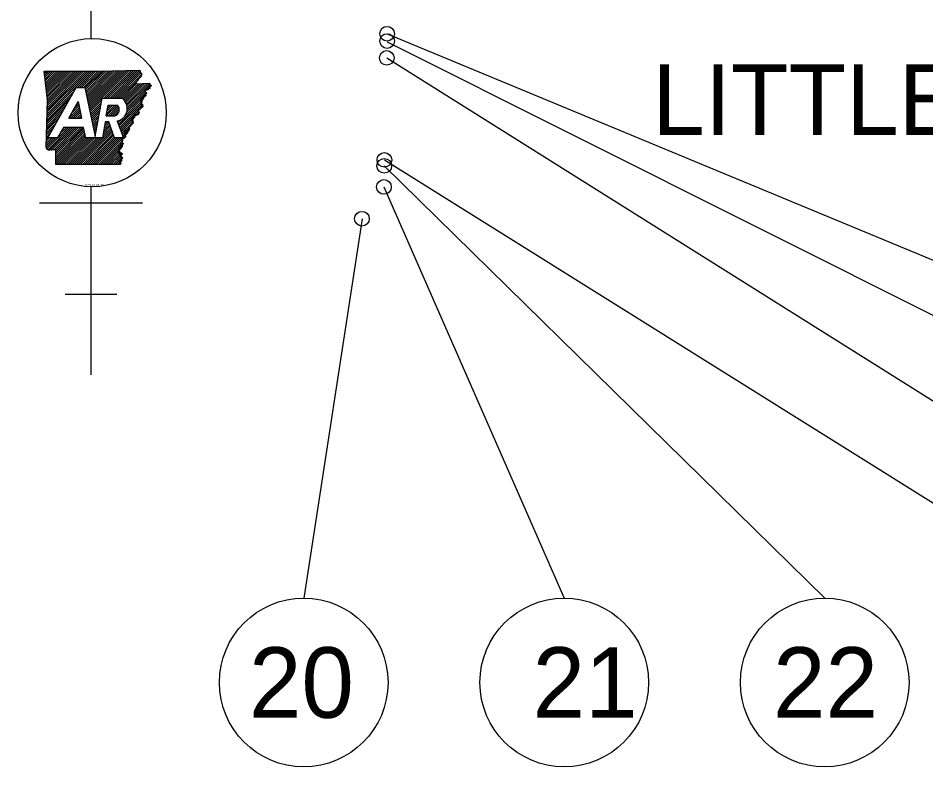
# Model space of a CAD drawing. Extents: x -12863 to 18921, y -8840 to 11152.
# Drawn here: x -1568 to 1521, y -4899 to -2352 of the extents above; entities that cross this region are included whole.
import ezdxf

# ---------------------------------------------------------------- set-up
doc = ezdxf.new("R2010")
doc.units = 0
doc.layers.add('Level 2', color=7, linetype='Continuous')
doc.layers.add('Level 48', color=7, linetype='Continuous')

msp = doc.modelspace()

# ---------------------------------------------------------------- linework, layer by layer
at = {"layer": 'Level 48'}
for p, q in [((-1319.7, -2421.2), (-1319.7, -845.3)), ((-312, -2404.6), (4520.7, -4409.4)), ((-312.1, -2432), (3634.1, -4409.4)), ((-313.2, -2486.8), (2747.5, -4409.4)), ((-1479.3, -2534.1), (-1477.2, -2531.9)), ((-1478.6, -2540.3), (-1470.2, -2531.9)), ((-1477.8, -2546.5), (-1463.2, -2531.9)), ((-1477, -2552.7), (-1456.3, -2531.9)), ((-1476.2, -2558.9), (-1449.3, -2531.9)), ((-1475.5, -2565.1), (-1442.3, -2531.9)), ((-1474.7, -2571.3), (-1435.4, -2532)), ((-1473.9, -2577.5), (-1428.4, -2532)), ((-1473.2, -2583.7), (-1421.5, -2532)), ((-1472.4, -2589.8), (-1414.5, -2532)), ((-1471.6, -2596), (-1407.5, -2532)), ((-1470.8, -2602.2), (-1400.6, -2532)), ((-1470.1, -2608.4), (-1393.6, -2532)), ((-1469.3, -2614.6), (-1386.7, -2532)), ((-1469.1, -2684), (-1316.9, -2531.8)), ((-1468.8, -2676.8), (-1323.8, -2531.9)), ((-1468.6, -2669.6), (-1330.8, -2531.9)), ((-1468.5, -2620.8), (-1379.7, -2532)), ((-1468.3, -2662.4), (-1337.8, -2531.9)), ((-1468.1, -2655.2), (-1344.8, -2531.9)), ((-1467.9, -2648), (-1351.8, -2531.9)), ((-1467.8, -2627), (-1372.7, -2532)), ((-1467.6, -2640.8), (-1358.7, -2531.9)), ((-1467.4, -2633.6), (-1365.7, -2531.9)), ((-1365.6, -2587.6), (-1309.9, -2531.8)), ((-1358.7, -2587.6), (-1302.9, -2531.8)), ((-1351.7, -2587.6), (-1295.9, -2531.8)), ((-1344.7, -2587.6), (-1288.8, -2531.6)), ((-1340.4, -2590.2), (-1281.7, -2531.5)), ((-1339.2, -2595.9), (-1274.6, -2531.4)), ((-1337.9, -2601.7), (-1267.6, -2531.3)), ((-1336.7, -2607.4), (-1260.5, -2531.2)), ((-1335.5, -2613.2), (-1253.4, -2531.1)), ((-1334.2, -2618.9), (-1246.3, -2531)), ((-1333, -2624.6), (-1239.3, -2530.9)), ((-1331.8, -2630.4), (-1232.2, -2530.8)), ((-1330.6, -2636.1), (-1225.1, -2530.7)), ((-1329.3, -2641.8), (-1218, -2530.5)), ((-1328.1, -2647.6), (-1211, -2530.4)), ((-1326.9, -2653.3), (-1203.9, -2530.3)), ((-1325.7, -2659.1), (-1196.8, -2530.2)), ((-1324.4, -2664.8), (-1189.7, -2530)), ((-1276, -2623.4), (-1182.5, -2529.9)), ((-1269.1, -2623.4), (-1175.4, -2529.7)), ((-1262.1, -2623.4), (-1168.3, -2529.5)), ((-1255.1, -2623.4), (-1161.1, -2529.4)), ((-1248.2, -2623.4), (-1154, -2529.2)), ((-1241.2, -2623.4), (-1152.5, -2534.6)), ((-1234.2, -2623.4), (-1149.1, -2538.2)), ((-1227.3, -2623.4), (-1148.2, -2544.3)), ((-1467, -2759.2), (-1369.8, -2587.6)), ((-1369.8, -2587.6), (-1341, -2587.6)), ((-1220.3, -2623.4), (-1164.1, -2567.1)), ((-1214, -2624), (-1165.5, -2575.5)), ((-1210.2, -2627.2), (-1158.1, -2575.1)), ((-1206.8, -2630.7), (-1150.8, -2574.7)), ((-1203.8, -2634.7), (-1143.4, -2574.4)), ((-1201.2, -2639.1), (-1136.1, -2574)), ((-1199.1, -2643.9), (-1128.7, -2573.6)), ((-1197.5, -2649.3), (-1122.1, -2574)), ((-1196.5, -2655.3), (-1118.9, -2577.7)), ((-1122, -2587.7), (-1115.6, -2581.4)), ((-1469.5, -2698.5), (-1384.4, -2613.3)), ((-1469.3, -2691.3), (-1375.3, -2597.3)), ((-1282.3, -2623.4), (-1214.9, -2623.4)), ((-1197.9, -2670.6), (-1134.7, -2607.4)), ((-1196.5, -2662.2), (-1135.5, -2601.3)), ((-1142.5, -2622.2), (-1133.9, -2613.6)), ((-1470, -2712.9), (-1402.6, -2645.4)), ((-1469.8, -2705.7), (-1393.5, -2629.4)), ((-1395.5, -2691.8), (-1363.7, -2635.7)), ((-1395.2, -2691.8), (-1359.4, -2656)), ((-1386.9, -2676.5), (-1360.6, -2650.3)), ((-1377.8, -2660.5), (-1361.8, -2644.5)), ((-1368.7, -2644.4), (-1363.1, -2638.8)), ((-1323.2, -2670.5), (-1283.7, -2631)), ((-1322, -2676.3), (-1285.1, -2639.4)), ((-1320.7, -2682), (-1286.6, -2647.9)), ((-1319.5, -2687.7), (-1288.1, -2656.3)), ((-1267.7, -2684.2), (-1231, -2647.6)), ((-1266.2, -2675.8), (-1238, -2647.6)), ((-1264.8, -2667.4), (-1244.9, -2647.6)), ((-1263.3, -2659), (-1251.9, -2647.6)), ((-1261.8, -2650.5), (-1258.9, -2647.6)), ((-1261.3, -2647.6), (-1229.6, -2647.6)), ((-1260.7, -2684.2), (-1227.1, -2650.7)), ((-1253.7, -2684.2), (-1224.8, -2655.3)), ((-1226.7, -2713.3), (-1149.5, -2636.1)), ((-1224.8, -2718.4), (-1148.2, -2641.8)), ((-1222.9, -2723.5), (-1146.9, -2647.4)), ((-1221, -2728.6), (-1145.6, -2653.1)), ((-1204, -2683.7), (-1150.8, -2630.4)), ((-1470.5, -2727.3), (-1420.8, -2677.6)), ((-1470.3, -2720.1), (-1411.7, -2661.5)), ((-1388.2, -2691.8), (-1358.2, -2661.8)), ((-1381.2, -2691.8), (-1356.9, -2667.5)), ((-1374.3, -2691.8), (-1355.7, -2673.2)), ((-1367.3, -2691.8), (-1354.5, -2679)), ((-1360.3, -2691.8), (-1353.2, -2684.7)), ((-1318.3, -2693.5), (-1289.6, -2664.7)), ((-1317.1, -2699.2), (-1291, -2673.2)), ((-1315.8, -2705), (-1292.5, -2681.6)), ((-1267.7, -2684.2), (-1238.8, -2684.2)), ((-1246.8, -2684.2), (-1223.5, -2661)), ((-1239.8, -2684.2), (-1224.1, -2668.5)), ((-1169.4, -2683.9), (-1159.6, -2674.1)), ((-1471, -2741.7), (-1439, -2709.7)), ((-1470.7, -2734.5), (-1429.9, -2693.6)), ((-1395.5, -2691.8), (-1351.7, -2691.8)), ((-1353.4, -2691.8), (-1352, -2690.5)), ((-1314.6, -2710.7), (-1294, -2690.1)), ((-1313.4, -2716.4), (-1295.4, -2698.5)), ((-1312.1, -2722.2), (-1296.9, -2706.9)), ((-1310.9, -2727.9), (-1298.4, -2715.4)), ((-1276.6, -2735.4), (-1255.8, -2714.6)), ((-1275.1, -2727), (-1257.7, -2709.5)), ((-1273.7, -2718.5), (-1259.7, -2704.6)), ((-1272.2, -2710.1), (-1266.7, -2704.6)), ((-1259.6, -2704.6), (-1271.2, -2704.6)), ((-1239.4, -2759.2), (-1259.6, -2704.6)), ((-1231, -2701.7), (-1209.7, -2759.2)), ((-1230.4, -2703.2), (-1228.3, -2701)), ((-1228.6, -2708.2), (-1215.3, -2695)), ((-1219.2, -2733.7), (-1177.4, -2691.9)), ((-1217.3, -2738.8), (-1178.2, -2699.6)), ((-1215.4, -2743.8), (-1178.9, -2707.4)), ((-1471.5, -2756.1), (-1457.2, -2741.8)), ((-1471.2, -2748.9), (-1448.1, -2725.7)), ((-1469.9, -2796.4), (-1396.7, -2723.2)), ((-1465.8, -2799.2), (-1389.8, -2723.2)), ((-1460.8, -2801.2), (-1382.8, -2723.2)), ((-1452.5, -2799.9), (-1375.8, -2723.2)), ((-1445.5, -2799.8), (-1368.9, -2723.2)), ((-1440, -2801.3), (-1361.9, -2723.2)), ((-1439.8, -2808), (-1354.9, -2723.2)), ((-1439.7, -2814.9), (-1348, -2723.2)), ((-1439.7, -2821.9), (-1344.3, -2726.5)), ((-1439.7, -2828.8), (-1343.1, -2732.2)), ((-1439.7, -2835.8), (-1341.9, -2737.9)), ((-1439.7, -2842.7), (-1340.6, -2743.7)), ((-1413.3, -2723.2), (-1433.7, -2759.2)), ((-1425.8, -2745.2), (-1403.7, -2723.2)), ((-1416.7, -2729.2), (-1410.7, -2723.2)), ((-1345, -2723.2), (-1413.3, -2723.2)), ((-1370, -2849.7), (-1250.2, -2729.9)), ((-1363.1, -2849.7), (-1248.3, -2735)), ((-1356.1, -2849.7), (-1246.4, -2740.1)), ((-1349.2, -2849.7), (-1244.6, -2745.1)), ((-1309.7, -2733.6), (-1299.8, -2723.8)), ((-1308.5, -2739.4), (-1301.3, -2732.2)), ((-1307.2, -2745.1), (-1302.8, -2740.7)), ((-1306, -2750.9), (-1304.3, -2749.1)), ((-1279.6, -2752.3), (-1252.1, -2724.8)), ((-1278.1, -2743.8), (-1254, -2719.7)), ((-1213.5, -2748.9), (-1192.2, -2727.6)), ((-1211.7, -2754), (-1195.2, -2737.5)), ((-1472.5, -2792), (-1439.7, -2759.2)), ((-1472.4, -2784.9), (-1446.7, -2759.2)), ((-1472.2, -2777.7), (-1453.6, -2759.2)), ((-1471.9, -2770.5), (-1460.6, -2759.2)), ((-1471.7, -2763.3), (-1466.2, -2757.8)), ((-1433.7, -2759.2), (-1467, -2759.2)), ((-1439.6, -2849.6), (-1339.4, -2749.4)), ((-1432.6, -2849.6), (-1338.2, -2755.2)), ((-1425.7, -2849.6), (-1335.2, -2759.2)), ((-1418.7, -2849.6), (-1328.3, -2759.2)), ((-1411.7, -2849.6), (-1321.3, -2759.2)), ((-1404.8, -2849.6), (-1314.3, -2759.2)), ((-1397.8, -2849.6), (-1307.4, -2759.2)), ((-1390.9, -2849.7), (-1300.4, -2759.2)), ((-1383.9, -2849.7), (-1293.4, -2759.2)), ((-1377, -2849.7), (-1286.5, -2759.2)), ((-1342.2, -2849.7), (-1242.7, -2750.2)), ((-1280.8, -2759.2), (-1337.3, -2759.2)), ((-1335.2, -2849.8), (-1240.8, -2755.3)), ((-1328.3, -2849.8), (-1237.7, -2759.2)), ((-1321.3, -2849.8), (-1230.7, -2759.2)), ((-1314.4, -2849.8), (-1223.8, -2759.2)), ((-1307.4, -2849.8), (-1216.8, -2759.2)), ((-1300.5, -2849.8), (-1214.5, -2763.8)), ((-1293.5, -2849.8), (-1214.2, -2770.5)), ((-1286.6, -2849.8), (-1213.8, -2777.1)), ((-1209.7, -2759.2), (-1239.4, -2759.2)), ((-1279.6, -2849.8), (-1213.5, -2783.8)), ((-1272.7, -2849.9), (-1225, -2802.2)), ((-1265.7, -2849.9), (-1222.8, -2807)), ((-1258.7, -2849.9), (-1220.7, -2811.8)), ((-1251.8, -2849.9), (-1218.5, -2816.6)), ((-1244.8, -2849.9), (-1216.4, -2821.4)), ((-1237.9, -2849.9), (-1214.6, -2826.6)), ((-1230.9, -2849.9), (-1217.7, -2836.7)), ((-321.4, -2833.9), (2063.8, -4325.4)), ((-1224, -2849.9), (-1220.9, -2846.8)), ((-321.7, -2854.1), (1177.2, -4325.4)), ((-1319.7, -3564.9), (-1319.7, -2925.3)), ((-322.9, -2926.1), (290.7, -4325.4)), ((-1495.1, -2979.7), (-1144.2, -2979.7)), ((-397.5, -3035), (-595.9, -4325.4)), ((-1407.4, -3291.3), (-1232, -3291.3))]:
    msp.add_line(p, q, dxfattribs=at)
for points in [[(-1479.6, -2532), (-1383.5, -2532), (-1299.1, -2531.8), (-1199.7, -2530.3), (-1153.6, -2529.2)], [(-1479.6, -2531.9), (-1383.5, -2532), (-1299.2, -2531.8), (-1199.7, -2530.3), (-1153.6, -2529.2)], [(-1472.6, -2791.9), (-1467.3, -2630.7), (-1479.6, -2531.9)], [(-1469, -2681.3), (-1467.3, -2630.7), (-1479.6, -2532)], [(-1341, -2587.6), (-1305.2, -2754.6), (-1282.3, -2623.4)], [(-1123.4, -2573.3), (-1115.1, -2582), (-1135.8, -2599.1), (-1133.5, -2616.3), (-1151.3, -2628), (-1145.2, -2654.5), (-1158.9, -2667), (-1160.2, -2680.6), (-1176.8, -2686.6), (-1179.4, -2712.2), (-1191.4, -2725), (-1197.2, -2744.4), (-1214.6, -2760.3), (-1213.3, -2788.5), (-1225.2, -2801.8), (-1214.4, -2825.9), (-1221.8, -2849.9)], [(-1167.8, -2575.6), (-1122.7, -2573.3)], [(-1167.8, -2575.6), (-1122.7, -2573.3)], [(-1363.7, -2635.7), (-1351.7, -2691.8)], [(-1267.7, -2684.2), (-1261.3, -2647.6)], [(-1472.6, -2791.9), (-1469, -2681.3)], [(-1271.2, -2704.6), (-1280.8, -2759.2)], [(-1337.3, -2759.2), (-1345, -2723.2)], [(-1221.9, -2850), (-1439.7, -2849.6), (-1439.8, -2801.5)], [(-1221.8, -2849.9), (-1439.7, -2849.6), (-1439.8, -2801.5)]]:
    msp.add_lwpolyline(points, dxfattribs=at)
for centre, radius in [((-312, -2404.6), 25), ((-312, -2429.7), 25), ((-313.2, -2486.8), 25), ((-321.4, -2833.9), 25), ((-321.7, -2854.1), 25), ((-322.9, -2926.1), 25), ((-397.6, -3034.1), 25), ((-595.9, -4612.3), 286.9), ((290.7, -4612.3), 286.9), ((1177.2, -4612.3), 286.9)]:
    msp.add_circle(centre, radius, dxfattribs=at)
msp.add_ellipse((-1315.6, -2673.3), major_axis=(252.1, 0), ratio=0.999976, dxfattribs=at)
for centre, major_axis, start_param, end_param in [((-1239.9, -2659), (-43.6, 0), 1.777838, 4.099264), ((-1245.7, -2663), (-22.3, 0), 1.887169, 3.90762)]:
    msp.add_ellipse(centre, major_axis=major_axis, ratio=0.999987, start_param=start_param, end_param=end_param, dxfattribs=at)
for points in [[(-1153.6, -2529.2), (-1153.3, -2531.8), (-1152.5, -2533.2), (-1152.4, -2535.7), (-1151.3, -2536.8), (-1149.5, -2537.8), (-1148.1, -2539.5), (-1147.7, -2541.5), (-1148.2, -2543.6), (-1148.3, -2546), (-1148.5, -2548), (-1148.9, -2549.8), (-1150.3, -2551.3), (-1151.6, -2552.4), (-1152.9, -2553.6), (-1153.8, -2554.9), (-1155.3, -2556.3), (-1156.9, -2557.9), (-1158.2, -2559.1), (-1159.4, -2560.8), (-1160, -2562.6), (-1161.3, -2564), (-1162.4, -2565.2), (-1163.8, -2566.8), (-1164.5, -2568.3), (-1165.9, -2570.2), (-1166.2, -2572), (-1167.1, -2573.4), (-1167.2, -2573.6)], [(-1153.6, -2529.2), (-1153.3, -2531.8), (-1152.4, -2533.2), (-1152.3, -2535.7), (-1151.3, -2536.7), (-1149.6, -2537.8), (-1148, -2539.5), (-1147.7, -2541.6), (-1148.2, -2543.6), (-1148.3, -2546), (-1148.5, -2548), (-1148.9, -2549.8), (-1150.3, -2551.3), (-1151.7, -2552.4), (-1152.9, -2553.6), (-1153.8, -2554.9), (-1155.3, -2556.4), (-1156.9, -2557.8), (-1158.1, -2559.1), (-1159.4, -2560.8), (-1160, -2562.7), (-1161.3, -2564), (-1162.4, -2565.1), (-1163.8, -2566.8), (-1164.6, -2568.4), (-1165.9, -2570.2), (-1166.2, -2572), (-1167.1, -2573.4), (-1167.2, -2573.6)], [(-1123.4, -2573.3), (-1122.7, -2573.3), (-1120.7, -2575.4), (-1119.8, -2577.2), (-1118.5, -2578.2), (-1117, -2578.7), (-1115.9, -2580.1), (-1115.1, -2581.6), (-1115.5, -2582.9), (-1117.2, -2583), (-1119, -2583.3), (-1120.8, -2583.3), (-1122.3, -2584.5), (-1120.9, -2586.1), (-1119.2, -2587.6), (-1118.7, -2589.2), (-1119.7, -2590.7), (-1121.6, -2591.5), (-1123.4, -2592.3), (-1125.1, -2593.7), (-1125.9, -2595.1), (-1127.7, -2595.6), (-1129.6, -2596.2), (-1131.3, -2596.3), (-1133.2, -2596.7), (-1135, -2597.6), (-1135.8, -2599.1), (-1135.5, -2601.3), (-1135.6, -2603.7), (-1133.7, -2604.4), (-1131.9, -2604.5), (-1130.2, -2605.4), (-1130.5, -2606.7), (-1131.7, -2608.4), (-1133.2, -2609.7), (-1134.7, -2610.3), (-1136, -2611.6), (-1135.5, -2612.8), (-1134.3, -2613.6), (-1133.4, -2615), (-1133.5, -2616.2), (-1135, -2617.1), (-1136.5, -2616.8), (-1137.7, -2615.3), (-1138.9, -2614.9), (-1140.1, -2614.3), (-1141.4, -2615.1), (-1141.4, -2616.8), (-1141.8, -2618.6), (-1141.4, -2620), (-1141, -2621.9), (-1141, -2623.3), (-1141.4, -2625.4), (-1142.5, -2627.5), (-1143.6, -2628.1), (-1144.2, -2625.8), (-1144.3, -2624), (-1145.1, -2622.9), (-1146, -2622.9), (-1147.3, -2623.7), (-1148.6, -2625.1), (-1150.3, -2626.6), (-1151.4, -2628.1), (-1150.8, -2629.9), (-1149.5, -2630.4), (-1148.5, -2630.1), (-1148, -2628.9), (-1147, -2628.7), (-1146, -2630.5)], [(-1146, -2630.5), (-1145.8, -2632.2), (-1146.8, -2634.1), (-1147.2, -2635.9), (-1147, -2637.8), (-1148.9, -2638.8), (-1150.5, -2640), (-1149.5, -2641.4), (-1147.8, -2642.7), (-1146, -2643.7), (-1144.9, -2644.7), (-1144.6, -2647.1), (-1144.3, -2648.7), (-1143.7, -2650.9), (-1143.5, -2652.3), (-1144.5, -2654.1), (-1145.8, -2654.5), (-1147.1, -2654.1), (-1148.6, -2653.9), (-1149.9, -2655.1), (-1150.8, -2656.8), (-1151.6, -2658.5), (-1152.4, -2659.9), (-1153, -2661.4), (-1154.3, -2663.2), (-1155.9, -2663.5), (-1157.8, -2664), (-1158.9, -2665.3), (-1158.7, -2667.5), (-1157.6, -2669), (-1156.8, -2670.8), (-1156.2, -2672.4), (-1156.5, -2674.4), (-1157.3, -2675.9), (-1158.4, -2676.8), (-1158.9, -2678.7), (-1159.7, -2680.2), (-1160.4, -2680.6), (-1161.8, -2680.5), (-1163.4, -2680.2), (-1164.7, -2680.3), (-1165.9, -2681), (-1167.2, -2680.6), (-1168.5, -2679.1), (-1169.6, -2678.1), (-1170.8, -2677.7), (-1172, -2678.3), (-1172.2, -2680.3), (-1171.6, -2682.3), (-1171.1, -2685), (-1171.6, -2686.7), (-1171.8, -2689.4)], [(-1171.8, -2689.4), (-1173.9, -2691), (-1174.8, -2692.6), (-1180.1, -2692.2), (-1180, -2694), (-1181.8, -2695), (-1183.5, -2696.2), (-1182.6, -2697.7), (-1180.8, -2698.9), (-1179, -2699.9), (-1177.9, -2700.9), (-1177.6, -2703.4), (-1177.3, -2705), (-1176.7, -2707.1), (-1176.4, -2708.6), (-1177.5, -2710.3), (-1178.8, -2710.7), (-1180, -2710.3), (-1181.6, -2710.2), (-1182.8, -2711.3), (-1183.7, -2713), (-1184.6, -2714.7), (-1185.3, -2716.1), (-1186, -2717.7), (-1187.2, -2719.5), (-1188.8, -2719.7), (-1190.7, -2720.2), (-1191.9, -2721.5), (-1191.7, -2723.7), (-1190.6, -2725.2), (-1189.8, -2727.1), (-1189.2, -2728.7), (-1189.5, -2730.7), (-1190.3, -2732.2), (-1191.4, -2733.1), (-1191.9, -2735), (-1192.7, -2736.4), (-1193.4, -2736.9), (-1194.8, -2736.7), (-1196.3, -2736.4), (-1197.6, -2736.6), (-1198.9, -2737.2), (-1200.1, -2736.8), (-1201.4, -2735.4), (-1202.5, -2734.3), (-1203.7, -2733.9), (-1205, -2734.5), (-1205.2, -2736.5), (-1204.6, -2738.5), (-1204.1, -2741.3), (-1204.6, -2742.9), (-1204.8, -2745.7)], [(-1204.8, -2745.7), (-1204.9, -2745.8), (-1206, -2747.1), (-1205.4, -2749.2), (-1203.1, -2750), (-1202, -2752), (-1202, -2753.8), (-1202.7, -2756.3), (-1203.8, -2757.4), (-1205.9, -2757.9), (-1207.4, -2758.2), (-1207.7, -2760.9), (-1208.4, -2762.3), (-1209.7, -2762.7), (-1211.4, -2761.8), (-1212.5, -2761.3), (-1213.8, -2760.8), (-1215.5, -2759.8), (-1216.8, -2760), (-1216.4, -2762.6), (-1216.3, -2762.7), (-1214.8, -2764.6), (-1213.4, -2766.2), (-1212.8, -2768)], [(-1204.8, -2745.7), (-1204.9, -2745.8), (-1206, -2747.1), (-1205.4, -2749.2), (-1203.1, -2750), (-1202, -2752), (-1202, -2753.8), (-1202.7, -2756.3), (-1203.8, -2757.4), (-1205.9, -2757.9), (-1207.4, -2758.2), (-1207.7, -2760.9), (-1208.4, -2762.3), (-1209.7, -2762.7), (-1211.4, -2761.8), (-1212.5, -2761.3), (-1213.8, -2760.8), (-1215.5, -2759.8), (-1216.8, -2760), (-1216.4, -2762.6), (-1216.3, -2762.7), (-1214.8, -2764.6), (-1213.4, -2766.2), (-1212.8, -2768)], [(-1212.8, -2768), (-1213.3, -2769.4), (-1214, -2771.8), (-1213.8, -2773.8), (-1212.9, -2775.5), (-1211.5, -2776.5), (-1209.9, -2777.8), (-1210.1, -2779.9), (-1211, -2780.7), (-1213.1, -2780.2), (-1214.7, -2779.4), (-1216, -2779.9), (-1217.8, -2780.7), (-1219.2, -2781), (-1219.2, -2783.8), (-1217.4, -2785.8), (-1215.8, -2785.8), (-1213.9, -2786), (-1213.2, -2788.2), (-1214.3, -2790), (-1216.1, -2790.9), (-1218.3, -2789.8), (-1219.9, -2788.7), (-1221.5, -2787.6), (-1223.6, -2787.1), (-1224.7, -2787.3), (-1225.2, -2789.8), (-1224.3, -2792), (-1222.8, -2793.6), (-1221.3, -2795.6), (-1221.5, -2797.1), (-1222.6, -2797.5), (-1224.5, -2797.9), (-1225.6, -2798.5), (-1225.9, -2799), (-1225.3, -2801), (-1224.8, -2803.2), (-1224.8, -2804.9), (-1225.5, -2806.4), (-1226.5, -2808.8), (-1226.4, -2810.3), (-1225.6, -2811.1), (-1224.8, -2810.8), (-1223.6, -2810), (-1222.8, -2809), (-1222.1, -2807.8), (-1220.9, -2806.9), (-1219.4, -2807.7), (-1219, -2809.6), (-1219.9, -2811.2), (-1221.2, -2811.9), (-1222.7, -2812.5), (-1223.8, -2813.8), (-1223.5, -2815.4), (-1222.6, -2816.2), (-1220.4, -2815.8), (-1219, -2815.1), (-1218.1, -2814.3), (-1217.1, -2813.3), (-1216.6, -2812.2), (-1215.8, -2811.2), (-1214.4, -2810.9), (-1213.8, -2811.8), (-1214, -2813.8), (-1214.8, -2815.7), (-1216, -2817.3), (-1217.2, -2818.4), (-1218.8, -2820.9), (-1218.5, -2823.1), (-1217.8, -2825), (-1217.1, -2826.4), (-1215.6, -2826.1), (-1214, -2825.9), (-1213.1, -2826.7), (-1213.2, -2828.4), (-1214.3, -2830), (-1215.5, -2831.5), (-1216.1, -2833.6), (-1215.8, -2835.2), (-1215.8, -2836.5), (-1216.3, -2838), (-1217.1, -2838.8), (-1219.4, -2838.8), (-1221.7, -2838.5), (-1222.9, -2839.2), (-1222.7, -2841.3), (-1221.3, -2842.8), (-1220.4, -2843.5), (-1219, -2845.2), (-1218.4, -2846.5), (-1218.6, -2847.7), (-1219.4, -2848.8), (-1221.9, -2850)], [(-1212.8, -2768), (-1213.3, -2769.4), (-1214, -2771.8), (-1213.8, -2773.8), (-1212.9, -2775.5), (-1211.5, -2776.5), (-1209.9, -2777.8), (-1210.1, -2779.9), (-1211, -2780.7), (-1213.1, -2780.2), (-1214.7, -2779.4), (-1216, -2779.9), (-1217.8, -2780.7), (-1219.2, -2781), (-1219.2, -2783.8), (-1217.4, -2785.8), (-1215.8, -2785.8), (-1213.9, -2786), (-1213.2, -2788.2), (-1214.3, -2790), (-1216.1, -2790.9), (-1218.3, -2789.8), (-1219.9, -2788.7), (-1221.5, -2787.6), (-1223.6, -2787.1), (-1224.7, -2787.3), (-1225.2, -2789.8), (-1224.3, -2792), (-1222.8, -2793.6), (-1221.3, -2795.6), (-1221.5, -2797.1), (-1222.6, -2797.5), (-1224.5, -2797.9), (-1225.6, -2798.5), (-1225.9, -2799), (-1225.3, -2801), (-1224.8, -2803.2), (-1224.8, -2804.9), (-1225.5, -2806.4), (-1226.5, -2808.8), (-1226.4, -2810.3), (-1225.6, -2811.1), (-1224.8, -2810.8), (-1223.6, -2810), (-1222.8, -2809), (-1222.1, -2807.8), (-1220.9, -2806.9), (-1219.4, -2807.7), (-1219, -2809.6), (-1219.9, -2811.2), (-1221.2, -2811.9), (-1222.7, -2812.5), (-1223.8, -2813.8), (-1223.5, -2815.4), (-1222.6, -2816.2), (-1220.4, -2815.8), (-1219, -2815.1), (-1218.1, -2814.3), (-1217.1, -2813.3), (-1216.6, -2812.2), (-1215.8, -2811.2), (-1214.4, -2810.9), (-1213.8, -2811.8), (-1214, -2813.8), (-1214.8, -2815.7), (-1216, -2817.3), (-1217.2, -2818.4), (-1218.8, -2820.9), (-1218.5, -2823.1), (-1217.8, -2825), (-1217.1, -2826.4), (-1215.6, -2826.1), (-1214, -2825.9), (-1213.1, -2826.7), (-1213.2, -2828.4), (-1214.3, -2830), (-1215.5, -2831.5), (-1216.1, -2833.6), (-1215.8, -2835.2), (-1215.8, -2836.5), (-1216.3, -2838), (-1217.1, -2838.8), (-1219.4, -2838.8), (-1221.7, -2838.5), (-1222.9, -2839.2), (-1222.7, -2841.3), (-1221.3, -2842.8), (-1220.4, -2843.5), (-1219, -2845.2), (-1218.4, -2846.5), (-1218.6, -2847.7), (-1219.4, -2848.8), (-1221.9, -2850)], [(-1439.8, -2801.5), (-1439.5, -2801.6), (-1440.7, -2800.8), (-1442.2, -2800.1), (-1444, -2800), (-1446.2, -2799.7), (-1448, -2799.5), (-1449.9, -2798.2), (-1451.9, -2799.5), (-1454.2, -2800.5), (-1455.5, -2799.4), (-1457.2, -2800.1), (-1458.4, -2799.7), (-1460.5, -2801.2), (-1462.4, -2800.7), (-1463.8, -2801.1), (-1465.6, -2801), (-1466, -2799), (-1467.7, -2798.7), (-1469.2, -2797.9), (-1470.2, -2795.8), (-1470.9, -2794.2), (-1472.6, -2791.9)], [(-1439.8, -2801.5), (-1439.5, -2801.6), (-1440.7, -2800.8), (-1442.2, -2800.1), (-1443.9, -2800), (-1446.1, -2799.7), (-1448, -2799.5), (-1449.9, -2798.2), (-1451.9, -2799.5), (-1454.2, -2800.5), (-1455.5, -2799.4), (-1457.2, -2800.1), (-1458.4, -2799.8), (-1460.5, -2801.2), (-1462.4, -2800.7), (-1463.8, -2801.1), (-1465.6, -2801), (-1466, -2799), (-1467.7, -2798.7), (-1469.2, -2797.9), (-1470.2, -2795.8), (-1470.9, -2794.2), (-1472.6, -2791.9)]]:
    msp.add_spline(points, degree=3, dxfattribs=at)

# ---------------------------------------------------------------- texts
at = {"layer": 'Level 2'}
msp.add_text('LITTLE RIVER', height=240, dxfattribs=at).set_placement((590.7, -2748.8))
at = {"layer": 'Level 48'}
for s, height, p in [('STS 10-03-17', 7.288, (-1339.7, -2923.3)), ('20', 240, (-782.1, -4732.3)), ('21', 240, (183, -4732.3)), ('22', 240, (1001.5, -4732.3))]:
    msp.add_text(s, height=height, dxfattribs=at).set_placement(p)

doc.saveas('drawing.dxf')
